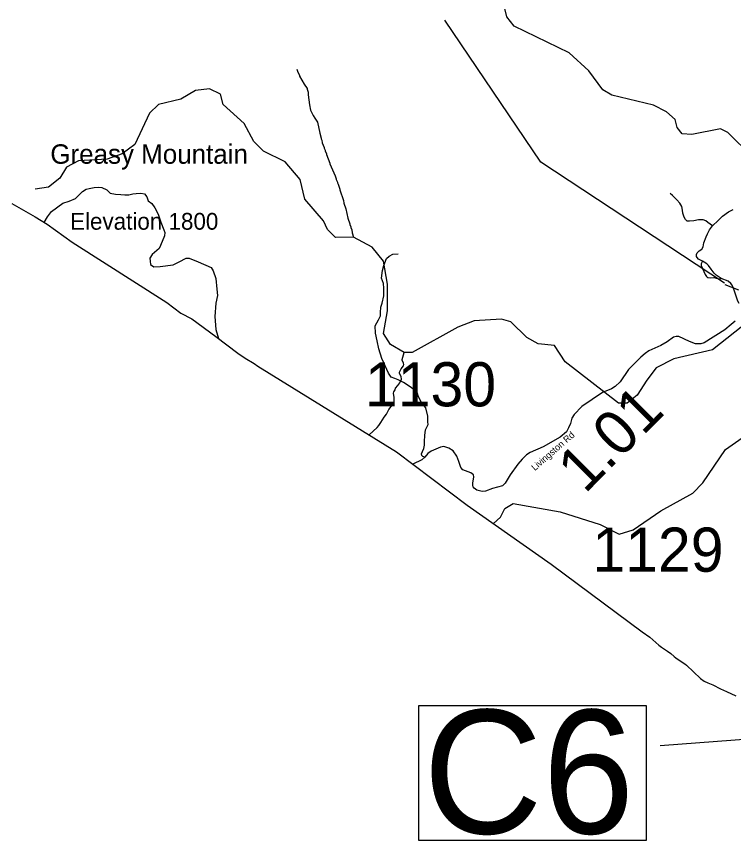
# Model space of a CAD drawing. Extents: x 1248224 to 1454986, y 825081 to 985870.
# Drawn here: x 1297811 to 1305942, y 834695 to 844031 of the extents above; entities that cross this region are included whole.
import ezdxf

# ---------------------------------------------------------------- set-up
doc = ezdxf.new("R2010")
doc.units = 0
for name, color, linetype in [('Exist Boundary Political CountyLine', 7, 'Continuous'), ('Exist Geographical Mountain Summit Elevation Number Label', 7, 'Continuous'), ('Exist Geographical Mountain Summit Label', 7, 'Continuous'), ('Exist Hydrographic Misc Water Feature', 7, 'Continuous'), ('Exist Road Non-System Type 51', 7, 'Continuous'), ('Exist Road Primary NC Structure Culvert Number Label', 7, 'Continuous'), ('Exist Road Secondary Mileage Hundredths English Label', 7, 'Continuous'), ('Exist Road Secondary Structure Culvert CELL', 7, 'Continuous'), ('Exist Road Secondary Structure Culvert Number Label', 7, 'Continuous'), ('Exist Road Secondary Type 51 Attributed', 7, 'Continuous'), ('Exist Road Secondary Type 51 Label', 7, 'Continuous'), ('Exist Road Secondary Type 51 Number Label', 7, 'Continuous')]:
    doc.layers.add(name, color=color, linetype=linetype)

msp = doc.modelspace()

# ---------------------------------------------------------------- linework, layer by layer
at = {"layer": 'Exist Boundary Political CountyLine'}
for points in [[(1297760.7, 841913.9), (1298024.7, 841760.6), (1298158.7, 841677.4), (1298442.7, 841474.2), (1299514.8, 840789.3), (1299675.8, 840669.7), (1299800.8, 840605.7), (1300072.8, 840404.1), (1300320.8, 840216.9), (1300404.8, 840160.4), (1300505.8, 840100.8), (1300547.8, 840068.8), (1302119.8, 839099.5), (1302922.9, 838493.8), (1303872.9, 837827.3), (1304906.9, 837061), (1304991.9, 836997.6), (1305095.9, 836907.2), (1305125.9, 836884), (1305193.9, 836840.9), (1305231.9, 836814.4), (1305270.9, 836781.4), (1305289.9, 836766.2), (1305324.9, 836739.2), (1305389.9, 836696.7), (1305409.9, 836681.2), (1305566, 836529.3)], [(1305566, 836529.3), (1305608.9, 836502), (1305651.9, 836480.4), (1305708.9, 836459.1), (1305793.9, 836412.3), (1305860.9, 836384.6), (1305969, 836335.3)]]:
    msp.add_lwpolyline(points, dxfattribs=at)
at = {"layer": 'Exist Hydrographic Misc Water Feature'}
for points in [[(1306842.9, 842302.4), (1306649.8, 842247.1), (1306508.8, 842269.7), (1306318.8, 842339.1), (1306153.9, 842444.2), (1305876.9, 842715.7), (1305794.8, 842760), (1305467.8, 842694.4), (1305359.8, 842703.1), (1305302.8, 842773.2), (1305279.8, 842865.6), (1305181.8, 842949.6), (1305033.8, 843028.1), (1304560.8, 843139.3), (1304461.8, 843200.4), (1304300.8, 843413.7), (1304079.8, 843618.4), (1303453.8, 843923.2), (1303372.8, 844026.5), (1303326.7, 844211.3)], [(1300991.9, 843435.6), (1300997.3, 843411.4), (1301020.2, 843362.9), (1301020, 843354.9), (1301074, 843265.6), (1301108.9, 843216.8), (1301108.8, 843208.8), (1301120, 843172.6), (1301119.2, 843142.6), (1301132.7, 843030.3), (1301147.3, 842968), (1301174, 842911.3), (1301193.3, 842878.9), (1301226.3, 842834.1), (1301251.5, 842709.6), (1301268.2, 842653.2), (1301268, 842645.2), (1301275.6, 842629), (1301279, 842600.9), (1301301.8, 842548.5), (1301301.6, 842540.5), (1301313.1, 842516.2), (1301312.9, 842508.2), (1301328.2, 842475.8), (1301328, 842467.8), (1301365.8, 842371), (1301365.6, 842363), (1301426.5, 842225.5), (1301437.8, 842193.3), (1301437.6, 842185.3), (1301452.9, 842153), (1301452.8, 842145), (1301460.3, 842130.8), (1301479.2, 842076.4), (1301479, 842068.4), (1301518.3, 841947.4), (1301523.5, 841915.4), (1301546.1, 841850.8), (1301567.7, 841746.3), (1301590.2, 841681.8), (1301590, 841673.9), (1301601.5, 841649.6), (1301601.3, 841641.6), (1301612.7, 841613.3), (1301617.9, 841581.2), (1301632.7, 841529.5)], [(1306118.8, 840583.6), (1305702.9, 840253.8), (1305266.8, 840154.3), (1305064.9, 840050), (1304960.9, 839911), (1304848.8, 839739.2), (1304737.9, 839649.5), (1304637.8, 839651.5), (1304031.8, 840116.7), (1303911.8, 840302.9), (1303727.8, 840323), (1303596.9, 840394.6), (1303416.8, 840572.2), (1303309.8, 840600.7), (1303000.8, 840583.8), (1302815.8, 840512.1), (1302299.8, 840223.7), (1302208.8, 840225.5), (1302051.8, 840314), (1301971.8, 840440.4), (1302018.8, 840695.4), (1302017.8, 840997.5), (1301973.8, 841257.7), (1301843.8, 841417.9), (1301632.7, 841529.5), (1301430.7, 841527.6), (1301338, 841617.1), (1301292.8, 841714.6), (1301081.8, 841961.7), (1301028.8, 842186), (1300857.8, 842383.1), (1300610.7, 842506.3), (1300504.7, 842616.7), (1300392.7, 842819.2), (1300155.7, 843034.1), (1300124.7, 843149.6), (1300001.7, 843211.2), (1299842.7, 843191.3), (1299673.7, 843096.3), (1299421.7, 843032.4), (1299319.7, 842936), (1299152.7, 842581.5), (1299008.7, 842476), (1298840.7, 842413.8), (1298514.8, 842397.3), (1298379.7, 842324.5), (1298301.7, 842201.3), (1298174.7, 842095.6), (1298023.7, 842075.7)], [(1301811, 839289.9), (1301900.1, 839375), (1301920.7, 839398.5), (1301943.3, 839430), (1301980.8, 839493.1), (1302005.5, 839524.5), (1302034.8, 839579.8), (1302084.2, 839642.6), (1302092.5, 839658.4), (1302093.7, 839714.4), (1302086.9, 839762.6), (1302091.3, 839778.5), (1302103.8, 839802.1), (1302108.2, 839820), (1302134.9, 839849.4), (1302157.5, 839880.9), (1302178.4, 839920.3), (1302175.2, 839952.4), (1302155.9, 839984.9), (1302156.3, 840000.9), (1302175.2, 840040.4), (1302199.9, 840071.8), (1302202.2, 840087.8), (1302198.6, 840103.9), (1302183.4, 840136.2), (1302183.6, 840144.2), (1302208.8, 840225.5)], [(1303218.9, 838286.1), (1303298.8, 838358.7), (1303350.8, 838456.2), (1303444.8, 838513.4), (1303975.9, 838417.4), (1304430.9, 838273.7), (1304645.9, 838167.6), (1304804.8, 838213.6), (1305118.9, 838430.5), (1305481.9, 838630.1), (1305592.9, 838746), (1305851.9, 839124.8), (1306190.9, 839364.2), (1306249.8, 839379.5)]]:
    msp.add_lwpolyline(points, dxfattribs=at)
at = {"layer": 'Exist Road Non-System Type 51'}
for points in [[(1298126.1, 841697.7), (1298163.4, 841762.3), (1298207.7, 841820.4), (1298337.8, 841914.6), (1298409.7, 841939.5), (1298478.9, 841967.2), (1298559.2, 842047.6), (1298603.5, 842075.3), (1298633.9, 842080.8), (1298692, 842091.9), (1298739.1, 842097.4), (1298777.8, 842094.6), (1298836, 842066.9), (1298874.7, 842030.9), (1298932.8, 842019.9), (1298996.5, 842014.3), (1299040.8, 842011.5), (1299085.1, 842011.5), (1299132.1, 842022.6), (1299168.1, 842025.4), (1299220.7, 842028.2), (1299265, 842022.6), (1299289.9, 841989.4), (1299303.7, 841942.3), (1299345.2, 841911.8), (1299378.5, 841862), (1299417.2, 841792.7), (1299447.7, 841701.3), (1299480.9, 841615.5), (1299494.7, 841582.2), (1299489.2, 841546.2), (1299444.9, 841435.4), (1299428.3, 841402.2), (1299350.8, 841335.7), (1299323.1, 841294.2), (1299325.9, 841258.2), (1299331.4, 841222.1), (1299367.4, 841194.4), (1299442.1, 841197.2), (1299588.8, 841216.6), (1299658, 841249.8), (1299735.5, 841291.4), (1299768.7, 841294.2), (1299871.1, 841252.6), (1300017.8, 841188.9), (1300042.7, 841150.1), (1300070.4, 841061.5), (1300081.5, 840942.4), (1300092, 840871.6), (1300072.6, 840782.9), (1300061.5, 840630.6), (1300072.6, 840483.8), (1300101.1, 840382.7)], [(1305702.9, 841659.7), (1305652.3, 841699), (1305627, 841717), (1305596.7, 841726.8), (1305544.4, 841726.8), (1305492.2, 841717), (1305443.3, 841710.4), (1305416.3, 841713.7), (1305396.1, 841730.1), (1305382.6, 841757.9), (1305365.7, 841802), (1305362.4, 841838), (1305355.6, 841877.3), (1305333.7, 841916.5), (1305298.3, 841952.5), (1305249.4, 842003.2), (1305223.3, 842026.1)], [(1305702.9, 841659.7), (1305766.9, 841718.6), (1305815.8, 841767.7), (1305886.6, 841816.7), (1305937.2, 841844.6)], [(1305589.1, 841257.3), (1305545.3, 841283.5), (1305528.4, 841299.9), (1305523.4, 841312.9), (1305521.7, 841334.2), (1305528.4, 841352.2), (1305552, 841375.1), (1305582.4, 841396.4), (1305597.5, 841420.9), (1305604.3, 841468.3), (1305631.2, 841535.4), (1305648.9, 841568.1), (1305670.9, 841615.6), (1305702.9, 841659.7)], [(1302441.3, 839037.1), (1302419.7, 839047.6), (1302409.2, 839058.1), (1302405, 839077), (1302415.5, 839104.4), (1302432.3, 839135.9), (1302436.5, 839173.8), (1302438.6, 839215.9), (1302440.7, 839283.2), (1302449.1, 839348.5), (1302478.6, 839407.4), (1302474.4, 839436.9), (1302476.5, 839504.2), (1302453.4, 839598.9), (1302398.7, 839664.1), (1302369.2, 839720.9), (1302356.6, 839769.3), (1302287.2, 839826.2), (1302201, 839883), (1302138.3, 839915.6), (1302100.4, 839928.2), (1302058.4, 839945), (1302028.9, 839989.2), (1301953.2, 840155.5), (1301919.6, 840264.9), (1301902.8, 840355.4), (1301881.7, 840441.7), (1301877.5, 840527.9), (1301917.5, 840596.2), (1301938.6, 840638.3), (1301940.7, 840676.2), (1301944.9, 840737.2), (1301959.6, 840781.4), (1301976.4, 840865.6), (1301976.4, 840951.8), (1301972.2, 841004.4), (1301949.1, 841067.6), (1301963.8, 841151.7), (1301976.4, 841208.6), (1302007.9, 841290.6), (1302037.4, 841315.9), (1302079.4, 841336.9), (1302138.3, 841343.2)], [(1305589.1, 841257.3), (1305575.6, 841227.9), (1305575.6, 841209.9), (1305590.8, 841175.5), (1305621.1, 841108.5), (1305636.3, 841087.2), (1305646.4, 841075.8), (1305656.5, 841072.5), (1305681.8, 841070.9), (1305718.9, 841072.5), (1305744.2, 841067.6), (1305772.8, 841057.8), (1305802.3, 841064.3)], [(1305802.3, 841064.3), (1305745, 841100.3), (1305721.4, 841124.8), (1305687.7, 841167.4), (1305657.4, 841211.5), (1305640.5, 841227.9), (1305609.3, 841249.1), (1305589.1, 841257.3)], [(1306006.3, 840778.1), (1305989.5, 840805.9), (1305977.7, 840851.7), (1305943.9, 840943.3), (1305925.4, 840987.4), (1305913.6, 841007.1), (1305881.6, 841031.6), (1305802.3, 841064.3)]]:
    msp.add_lwpolyline(points, dxfattribs=at)
at = {"layer": 'Exist Road Primary NC Structure Culvert Number Label'}
msp.add_line((1308261.4, 836004.1), (1305111.5, 835768.6), dxfattribs=at)
msp.add_lwpolyline([(1302373.7, 836224.4), (1304950.2, 836224.4), (1304950.2, 834695.1), (1302373.7, 834695.1)], close=True, dxfattribs=at)
at = {"layer": 'Exist Road Secondary Structure Culvert CELL'}
msp.add_line((1305843.9, 840994.5), (1305999.5, 840935.1), dxfattribs=at)
at = {"layer": 'Exist Road Secondary Structure Culvert Number Label'}
msp.add_lwpolyline([(1305838.7, 841008), (1303757.6, 842379.6), (1302669.8, 843987.7)], dxfattribs=at)
at = {"layer": 'Exist Road Secondary Type 51 Attributed'}
msp.add_lwpolyline([(1305961.6, 840580.4), (1305915.1, 840541.3), (1305844.7, 840481.8), (1305609.3, 840334.8), (1305572.2, 840323.3), (1305509.9, 840323.3), (1305444.1, 840347.9), (1305322.7, 840406.7), (1305292.4, 840406.7), (1305262.1, 840398.6), (1305191.3, 840344.6), (1305117.1, 840305.3), (1304981.4, 840243.2), (1304939.2, 840213.7), (1304892, 840172.8), (1304752.1, 840030.5), (1304656, 839893.1), (1304601.3, 839837.5), (1304559.1, 839811.3), (1304458, 839772.1), (1304223.6, 839613.4), (1304136.8, 839523.5), (1304109.9, 839480.9), (1304093, 839418.8), (1304072.8, 839369.7), (1304049.2, 839325.5), (1303977.5, 839263.4), (1303785.4, 839157.1), (1303637, 839091.6), (1303594.9, 839063.8), (1303544.3, 839016.4), (1303497.1, 838959.1), (1303408.6, 838838.1), (1303354.6, 838743.2), (1303320.9, 838715.4), (1303209.7, 838682.7), (1303130.4, 838651.6), (1303091.7, 838650), (1303031, 838663.1), (1303002.3, 838687.6), (1302990.5, 838704), (1302987.2, 838718.7), (1302985.5, 838744.8), (1302997.3, 838816.8), (1302992.2, 838839.7), (1302965.2, 838862.6), (1302872.5, 838893.7), (1302848.9, 838923.1), (1302827, 838990.2), (1302803.4, 839049.1), (1302763.8, 839111.2), (1302714.9, 839140.7), (1302655.9, 839158.7), (1302618.5, 839153.6), (1302514, 839107.6), (1302477.6, 839078.2), (1302441.3, 839037.1), (1302408, 839007.7), (1302305.9, 838959.1)], dxfattribs=at)

# ---------------------------------------------------------------- texts
at = {"layer": 'Exist Geographical Mountain Summit Elevation Number Label'}
msp.add_text('Elevation 1800', height=190, dxfattribs=at).set_placement((1298419.5, 841615.5))
at = {"layer": 'Exist Geographical Mountain Summit Label'}
msp.add_text('Greasy Mountain', height=220, dxfattribs=at).set_placement((1298195.6, 842362.8))
at = {"layer": 'Exist Road Primary NC Structure Culvert Number Label'}
msp.add_text('C6', height=1400, dxfattribs=at).set_placement((1302423.9, 834774.2))
at = {"layer": 'Exist Road Secondary Mileage Hundredths English Label'}
msp.add_text('1.01', height=500, rotation=45.0761, dxfattribs=at).set_placement((1304257.5, 838616.4))
at = {"layer": 'Exist Road Secondary Type 51 Label'}
msp.add_text('Livingston Rd', height=75, rotation=41.07569, dxfattribs=at).set_placement((1303689.7, 838879.7))
at = {"layer": 'Exist Road Secondary Type 51 Number Label'}
for s, p in [('1130', (1301762.5, 839614.2)), ('1129', (1304341.7, 837740.6))]:
    msp.add_text(s, height=500, dxfattribs=at).set_placement(p)

doc.saveas('drawing.dxf')
